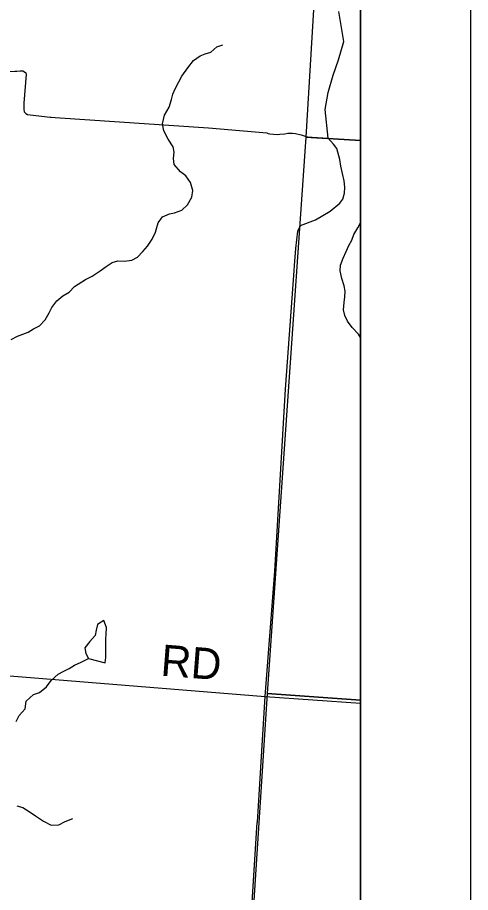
# Model space of a CAD drawing. Extents: x 0 to 42.5, y 0 to 22.
# Drawn here: x 8.588 to 9, y 17.417 to 18.213 of the extents above; entities that cross this region are included whole.
import ezdxf

# ---------------------------------------------------------------- set-up
doc = ezdxf.new("R2010")
doc.units = 0
for name, color, linetype in [('GM_X_Interchange_Ramps', 7, 'Continuous'), ('GM_X_Minor_Lake', 7, 'Continuous'), ('GM_X_Minor_River', 7, 'Continuous'), ('GM_X_Township_Road', 7, 'Continuous'), ('GM_X_Township_Road_Text', 7, 'Continuous'), ('GM_X_Unincorporated', 7, 'Continuous'), ('SH_Cut_Line', 7, 'Continuous'), ('SH_Data', 7, 'Continuous')]:
    doc.layers.add(name, color=color, linetype=linetype)

msp = doc.modelspace()

# ---------------------------------------------------------------- linework, layer by layer
at = {"layer": 'GM_X_Interchange_Ramps'}
msp.add_lwpolyline([(8.9, 15.53758), (8.9, 19.05381), (8.80207, 19.06082), (8.79715, 19.06117), (8.45529, 19.08562), (8.42249, 18.59682), (8.4216, 18.58362), (8.41233, 18.47844), (8.38323, 18.14846), (8.33786, 17.63394), (8.30797, 17.29222), (8.30866, 17.28459), (8.30841, 17.27648), (8.30737, 17.26941), (8.29023, 17.08765), (8.28773, 17.0646), (8.28228, 16.99116), (8.27401, 16.89234), (8.25723, 16.70556), (8.24802, 16.59431), (8.24781, 16.59008), (8.17933, 15.79111)], dxfattribs=at)
at = {"layer": 'GM_X_Minor_Lake'}
for p, q in [((8.66651, 17.66437), (8.66063, 17.66076)), ((8.66898, 17.65812), (8.66651, 17.66437)), ((8.66063, 17.66076), (8.6595, 17.65564)), ((8.66855, 17.65165), (8.66898, 17.65812)), ((8.65855, 17.6509), (8.65381, 17.6454)), ((8.6595, 17.65564), (8.65855, 17.6509)), ((8.66823, 17.64162), (8.66841, 17.64806)), ((8.66841, 17.64806), (8.66855, 17.65165)), ((8.65381, 17.6454), (8.64927, 17.63952)), ((8.66823, 17.63081), (8.66823, 17.64162)), ((8.64927, 17.63952), (8.65022, 17.63459)), ((8.65022, 17.63459), (8.65268, 17.62985)), ((8.65268, 17.62985), (8.66766, 17.62588)), ((8.66766, 17.62588), (8.66823, 17.63081))]:
    msp.add_line(p, q, dxfattribs=at)
at = {"layer": 'GM_X_Minor_River'}
for p, q in [((8.75875, 18.17966), (8.76387, 18.18134)), ((8.76387, 18.18134), (8.76939, 18.18625)), ((8.76939, 18.18625), (8.77471, 18.18813)), ((8.74296, 18.1672), (8.74811, 18.17382)), ((8.74811, 18.17382), (8.754, 18.17797)), ((8.754, 18.17797), (8.75875, 18.17966)), ((8.73743, 18.15964), (8.74296, 18.1672)), ((8.73457, 18.15434), (8.73743, 18.15964)), ((8.73151, 18.14809), (8.73457, 18.15434)), ((8.72806, 18.13843), (8.7294, 18.14317)), ((8.7294, 18.14317), (8.73151, 18.14809)), ((8.72594, 18.13142), (8.72806, 18.13843)), ((8.72155, 18.12404), (8.72594, 18.13142)), ((8.71982, 18.11608), (8.72155, 18.12404)), ((8.72093, 18.10982), (8.71982, 18.11608)), ((8.72507, 18.10222), (8.72093, 18.10982)), ((8.72959, 18.09538), (8.72507, 18.10222)), ((8.73033, 18.09044), (8.72959, 18.09538)), ((8.72974, 18.08457), (8.73033, 18.09044)), ((8.73048, 18.07906), (8.72974, 18.08457)), ((8.73614, 18.07259), (8.73048, 18.07906)), ((8.74105, 18.06878), (8.73614, 18.07259)), ((8.74539, 18.0627), (8.74105, 18.06878)), ((8.74745, 18.05567), (8.74539, 18.0627)), ((8.74647, 18.04961), (8.74745, 18.05567)), ((8.74246, 18.04242), (8.74647, 18.04961)), ((8.73751, 18.0375), (8.74246, 18.04242)), ((8.71604, 18.02602), (8.71986, 18.03169)), ((8.71986, 18.03169), (8.72612, 18.03432)), ((8.72612, 18.03432), (8.73087, 18.03525)), ((8.73087, 18.03525), (8.73751, 18.0375)), ((8.71336, 18.01768), (8.71604, 18.02602)), ((8.71048, 18.01125), (8.71336, 18.01768)), ((8.70629, 18.005), (8.71048, 18.01125)), ((8.69715, 17.9948), (8.70191, 18.00009)), ((8.70191, 18.00009), (8.70629, 18.005)), ((8.66867, 17.98656), (8.67419, 17.99015)), ((8.67419, 17.99015), (8.67912, 17.99145)), ((8.67912, 17.99145), (8.68519, 17.99124)), ((8.68519, 17.99124), (8.69183, 17.99216)), ((8.69183, 17.99216), (8.69715, 17.9948)), ((8.65574, 17.9777), (8.66316, 17.9826)), ((8.66316, 17.9826), (8.66867, 17.98656)), ((8.63997, 17.96828), (8.64985, 17.97469)), ((8.64985, 17.97469), (8.65574, 17.9777)), ((8.63483, 17.96318), (8.63997, 17.96828)), ((8.6238, 17.95506), (8.62932, 17.95978)), ((8.62932, 17.95978), (8.63483, 17.96318)), ((8.61923, 17.9492), (8.6238, 17.95506)), ((8.61311, 17.93785), (8.61674, 17.94428)), ((8.61674, 17.94428), (8.61923, 17.9492)), ((8.60797, 17.93256), (8.61311, 17.93785)), ((8.59277, 17.92503), (8.59771, 17.92672)), ((8.59771, 17.92672), (8.60265, 17.92973)), ((8.60265, 17.92973), (8.60797, 17.93256)), ((8.58232, 17.91995), (8.58803, 17.92315)), ((8.58803, 17.92315), (8.59277, 17.92503)), ((8.63973, 17.62388), (8.646, 17.62651)), ((8.646, 17.62651), (8.65268, 17.62985)), ((8.6251, 17.61559), (8.63004, 17.61842)), ((8.63004, 17.61842), (8.63498, 17.62087)), ((8.63498, 17.62087), (8.63973, 17.62388)), ((8.61443, 17.60407), (8.61863, 17.60993)), ((8.61863, 17.60993), (8.6251, 17.61559)), ((8.60797, 17.59916), (8.61443, 17.60407)), ((8.59599, 17.59124), (8.60246, 17.5971)), ((8.60246, 17.5971), (8.60797, 17.59916)), ((8.58949, 17.57799), (8.59482, 17.58423)), ((8.59482, 17.58423), (8.59599, 17.59124)), ((8.58681, 17.57269), (8.58949, 17.57799)), ((8.58746, 17.49607), (8.59276, 17.49454)), ((8.59276, 17.49454), (8.59938, 17.49015)), ((8.59938, 17.49015), (8.60448, 17.48691)), ((8.60448, 17.48691), (8.61167, 17.48214)), ((8.61167, 17.48214), (8.61867, 17.47851)), ((8.6255, 17.47867), (8.63139, 17.48168)), ((8.63139, 17.48168), (8.63822, 17.4845)), ((8.61867, 17.47851), (8.6255, 17.47867))]:
    msp.add_line(p, q, dxfattribs=at)
msp.add_lwpolyline([(8.9, 17.92179), (8.89804, 17.92481), (8.89238, 17.93109), (8.88823, 17.9366), (8.88578, 17.94192), (8.88448, 17.94705), (8.88507, 17.95368), (8.88566, 17.9588), (8.88587, 17.96411), (8.88513, 17.96885), (8.88288, 17.9755), (8.88139, 17.98252), (8.88179, 17.98764), (8.8841, 17.99408), (8.88696, 18.00014), (8.88926, 18.00544), (8.89193, 18.01036), (8.89385, 18.01547), (8.89748, 18.02153), (8.9, 18.02623)], dxfattribs=at)
at = {"layer": 'GM_X_Township_Road'}
for p, q in [((8.85598, 18.10394), (8.87057, 18.10323)), ((8.33797, 17.63368), (8.81327, 17.5954)), ((8.80612, 17.48125), (8.81327, 17.5954)), ((8.81327, 17.5954), (8.9, 17.58942))]:
    msp.add_line(p, q, dxfattribs=at)
for points in [[(8.84006, 17.98738), (8.84118, 18.00283), (8.84282, 18.01861), (8.84546, 18.02356), (8.85914, 18.02894), (8.87242, 18.03661), (8.88125, 18.04406), (8.88382, 18.04774), (8.8854, 18.05301), (8.88571, 18.05847), (8.885, 18.06446), (8.88206, 18.07754), (8.88104, 18.08366), (8.87838, 18.09371), (8.8755, 18.09779), (8.87057, 18.10323), (8.86781, 18.12931), (8.8704, 18.14472), (8.87509, 18.16032), (8.87997, 18.1744), (8.88464, 18.19096), (8.88014, 18.2183)], [(8.57212, 18.16315), (8.58547, 18.16406), (8.58745, 18.16416), (8.59043, 18.16424), (8.59268, 18.16428), (8.59447, 18.16353), (8.59551, 18.16264), (8.59573, 18.16131), (8.59388, 18.13499), (8.59373, 18.12936), (8.59418, 18.12706), (8.59544, 18.12557), (8.59707, 18.12454), (8.59952, 18.12424), (8.61754, 18.1222)], [(8.61754, 18.1222), (8.61849, 18.12209), (8.62213, 18.12187), (8.76161, 18.11246), (8.8148, 18.10788), (8.81607, 18.10745), (8.81752, 18.10712), (8.82075, 18.10678), (8.82434, 18.1066), (8.82645, 18.10678), (8.83108, 18.10716), (8.83396, 18.10753), (8.83699, 18.10767), (8.83804, 18.10762), (8.84075, 18.10723), (8.84585, 18.10613), (8.85068, 18.10478), (8.85343, 18.10416), (8.85452, 18.10402), (8.85598, 18.10394)], [(8.81327, 17.5954), (8.82198, 17.70935), (8.83188, 17.87491), (8.83971, 17.98256), (8.84006, 17.98738)], [(8.8329, 16.54439), (8.75198, 16.60851), (8.7558, 16.71165), (8.75666, 16.73142), (8.75777, 16.73769), (8.76191, 16.7474), (8.76238, 16.81144), (8.77085, 16.92466), (8.77199, 16.93824), (8.77352, 16.99486), (8.79121, 17.24348), (8.80609, 17.48076), (8.80612, 17.48125)]]:
    msp.add_lwpolyline(points, dxfattribs=at)
at = {"layer": 'GM_X_Unincorporated'}
for points in [[(8.9, 18.10104), (8.9, 18.55117), (8.87722, 18.55273), (8.85035, 18.10407)], [(8.9, 17.59215), (8.9, 18.10104), (8.85035, 18.10407), (8.81502, 17.59822)], [(8.9, 17.07703), (8.9, 17.59215), (8.81502, 17.59822), (8.78214, 17.08517)]]:
    msp.add_lwpolyline(points, close=True, dxfattribs=at)
at = {"layer": 'SH_Cut_Line'}
msp.add_lwpolyline([(8.9, 14.1), (8.9, 19.05381), (8.80207, 19.06082), (8.79715, 19.06117), (8.45529, 19.08562), (8.42249, 18.59682), (8.4216, 18.58362), (8.41233, 18.47844), (8.38323, 18.14846), (8.33786, 17.63394), (8.30797, 17.29222), (8.30866, 17.28459), (8.30841, 17.27648), (8.30737, 17.26941), (8.29023, 17.08765), (8.28773, 17.0646), (8.28228, 16.99116), (8.27401, 16.89234), (8.25723, 16.70556), (8.24802, 16.59431), (8.24781, 16.59008), (8.17933, 15.79111)], dxfattribs=at)
at = {"layer": 'SH_Data'}
for p, q in [((9, 21), (9, 14)), ((8.9, 20.9), (8.9, 14.1))]:
    msp.add_line(p, q, dxfattribs=at)

# ---------------------------------------------------------------- texts
at = {"layer": 'GM_X_Township_Road_Text'}
msp.add_text('RD', height=0.028409, rotation=355.56225, dxfattribs=at).set_placement((8.7176, 17.61444))

doc.saveas('drawing.dxf')
